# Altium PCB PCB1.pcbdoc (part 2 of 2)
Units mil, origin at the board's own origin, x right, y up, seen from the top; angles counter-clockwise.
Board outline 5331.95 x 5611.34 mil, 4 copper layers (Top Layer, GND, VCC, Bottom Layer); 134 components, 102 nets, 494 pads, 130 vias.
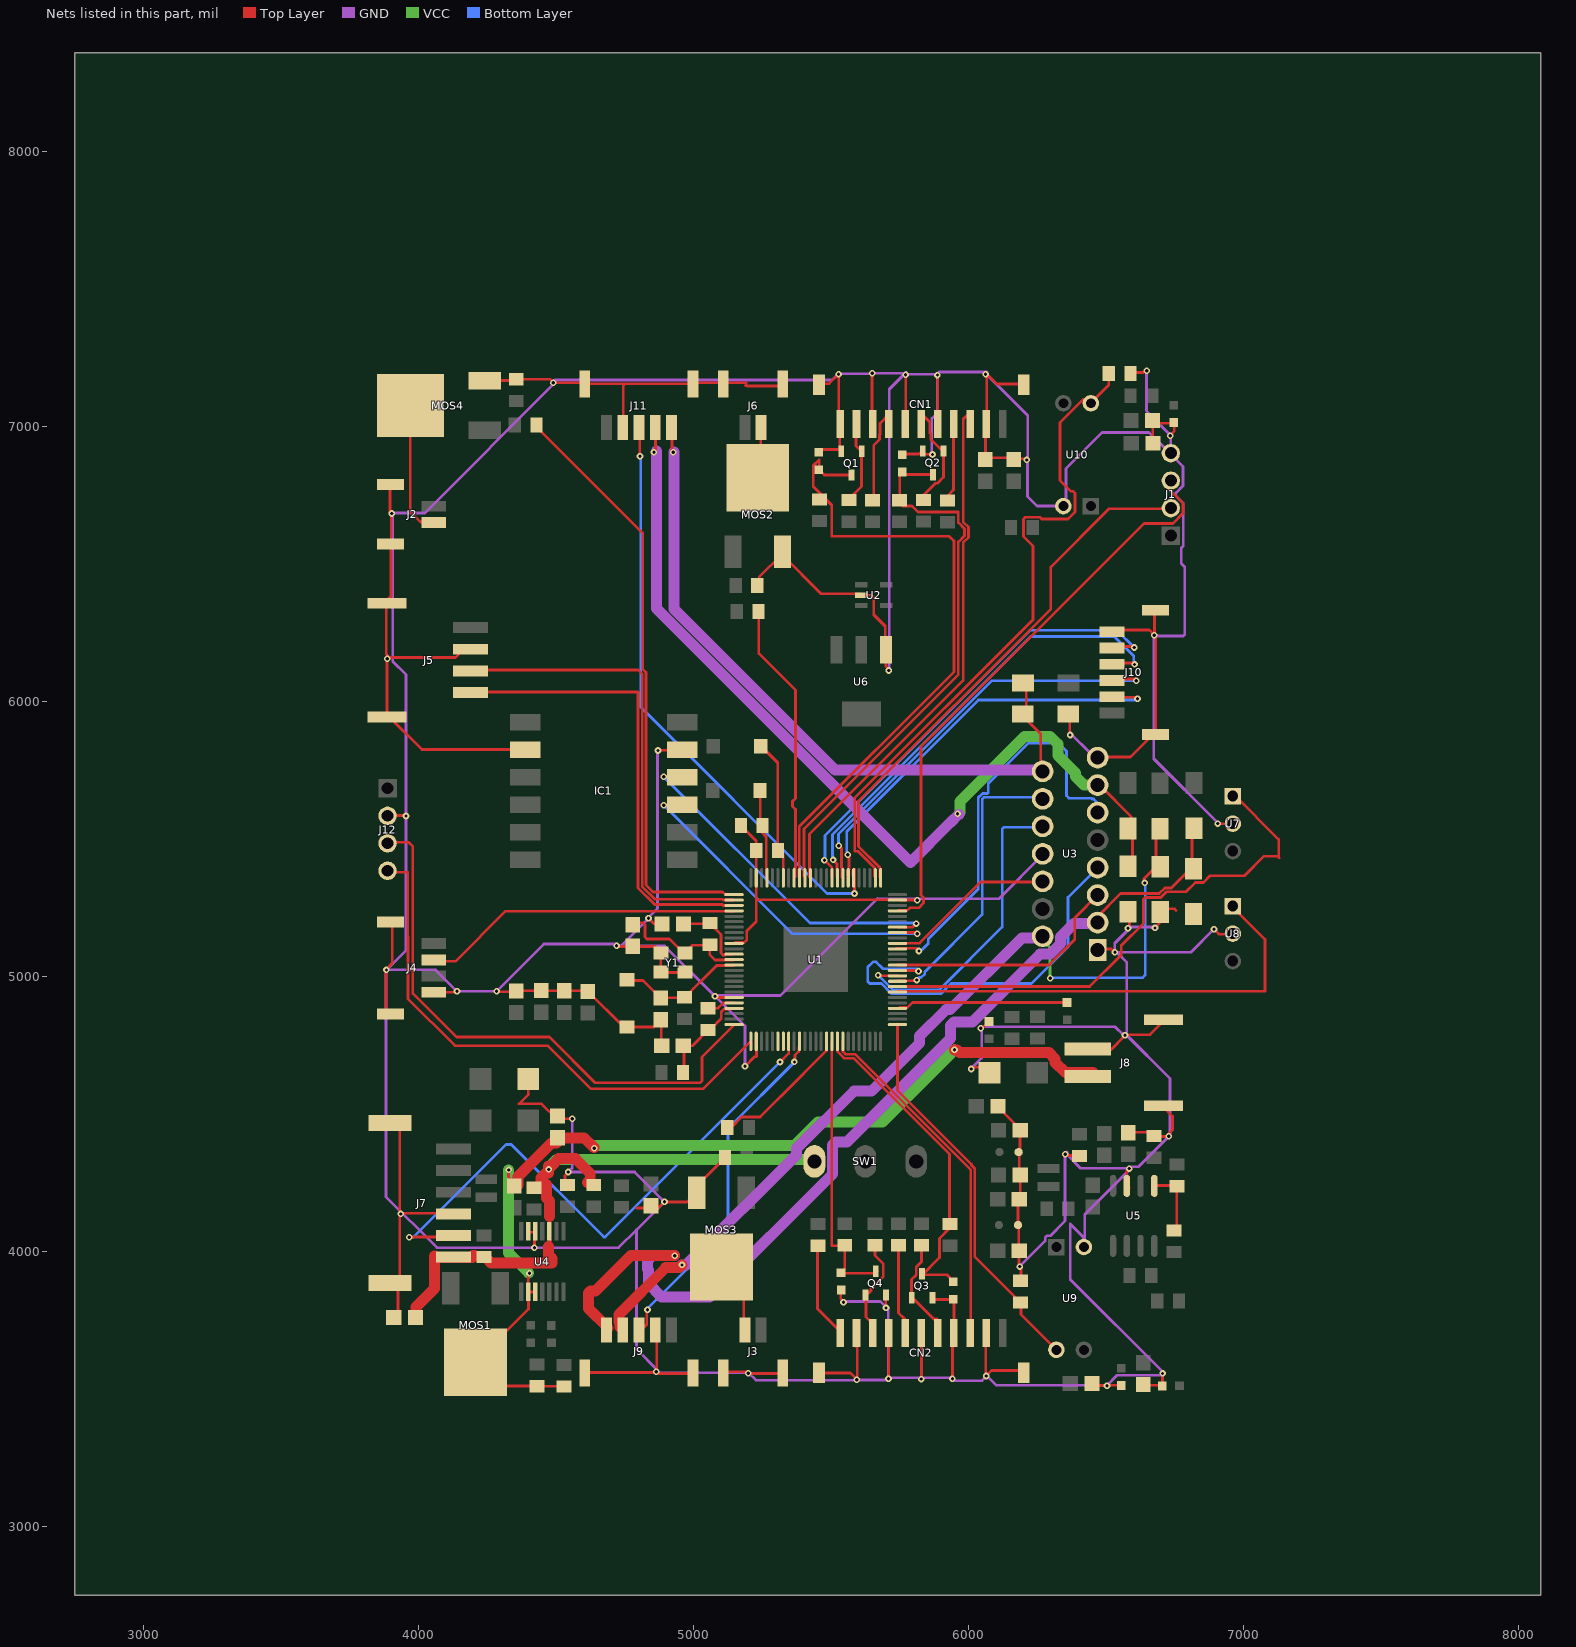
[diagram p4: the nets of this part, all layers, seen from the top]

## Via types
v1: diameter 24.02, hole 12.01, Top Layer to Bottom Layer, 130 vias

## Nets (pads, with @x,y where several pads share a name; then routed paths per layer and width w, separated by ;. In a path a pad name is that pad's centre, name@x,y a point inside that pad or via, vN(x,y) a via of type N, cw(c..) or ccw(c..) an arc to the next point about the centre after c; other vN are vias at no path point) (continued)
BAT0: J7.5 U1.33 | length 2084.2
  Top Layer w10: v1@3967.27,4053.06 4061.95,4053.06 J7.5@4066.07,4057.18 ; v1@5315.43,4689.12 5347.19,4720.88 U1.33@5347.19,4764.99
  Bottom Layer w10: v1@3966.79,4052.95 3982.35,4052.95 4319.1,4389.7 4338.14,4389.7 4674.89,4052.95 4678.68,4052.95 v1@5317.79,4692.07
  other v1: 3967.5,4052.88 5315.68,4689.91
BATTERY+: C12.1 J7.6 R14.1 R15.1 R16.1 SW1.1 U4.10 | length 2230.4
  Top Layer w10: 4204.74,3986.34 4214.22,3976.86 R16.1@4247.08,3976.86 ; 4449.08,4240.33 4462.17,4240.33 ; U4.10@4478.16,4046.06 4479.28,4044.95 4479.28,3984.03
  Top Layer w40: C12.1@3991.67,3760.1 3991.67,3798.69 4059.43,3866.45 4059.43,3984.11 ; J7.6@4078.26,3979.4 4197.79,3979.4 4204.74,3986.34 4199.09,3986.34 ; R16.1@4247.08,3976.86 4264.65,3959.29 4486.06,3959.29 4486.06,3976.01 4473.73,3988.33 4473.73,4019.01 ; R15.1@4446.57,4244.51 4446.57,4267.97 v1@4473.91,4295.34 ; 4466.31,4244.47 4466.31,4194.85 4477.28,4183.88 4477.28,4127.55 ; 4473.91,4286.39 v1@4473.91,4295.34 ; v1@4473.91,4311.21 v1@4473.91,4297.52 ; v1@4474.98,4298.58 v1@4473.91,4297.52 ; 4483.73,4311.21 4510.65,4338.13 4571.33,4338.13 4625.43,4284.02 4625.43,4261.49 R14.1@4615.97,4252.02 ; v1@4473.91,4295.34 v1@4473.91,4297.52
  VCC w40: v1(4474.29,4299.28) 4474.29,4306.18 4503.29,4335.18 5433.95,4335.18 SW1.1@5441.48,4327.65
BMQ-L1: J11.3 U1.81 | length 2175.6
  Top Layer w10: v1@4805.66,6894.2 J11.3@4805.66,6992.76 ; U1.81@5580.86,5367.84 5580.86,5385.26 5586.46,5390.86 5586.46,5303.15 v1(5586.56,5303.05)
  Bottom Layer w10: v1@4809.33,6886.4 4809.33,5980.35 5486.63,5303.05 v1(5586.56,5303.05)
  other v1: 4806.44,6893.22
BMQ-R1: J9.3 U1.35 | length 1241.1
  Top Layer w10: J9.3@4814.48,3719.83 4830.81,3736.16 v1@4830.81,3785.73 ; v1@5370.39,4694.8 5370.39,4715.34 5383.47,4728.42 5383.47,4742.61 U1.35@5386.46,4745.6
  Bottom Layer w10: v1@4836.19,3795.77 5126.85,4086.42 5126.85,4448.59 v1@5365.67,4687.41
  other v1: 4833.72,3788.84 5368.13,4690.28
BOOT0: KEY2.1 R7.1 U1.94 | length 517.9
  Top Layer w10: KEY2.1@5247.31,5838.57 5307.55,5778.34 R7.1@5307.55,5462.4 ; R7.1@5307.55,5454.56 R7.1@5307.55,5462.4 ; U1.94@5327.21,5361.59 5327.21,5442.74 R7.1@5307.55,5462.4
FAN_FB: J5.4 U1.3 | length 1709.6
  Top Layer w10: J5.4@4193.39,6035.97 4799.37,6035.97 4799.37,5323.14 4860.06,5262.45 5106.19,5262.45 5109.09,5259.56 5151.42,5259.56 5151.92,5259.06 U1.3@5163.63,5259.06
FAN_PWM: J5.3 U1.2 | length 1756
  Top Layer w10: J5.3@4193.17,6121.09 4198.81,6115.46 4800.24,6115.46 4814.21,6101.48 4814.21,5328.12 4860.2,5282.13 5105.7,5282.13 5108.7,5279.13 U1.2@5147.35,5279.13
FB: R41.1 R42.2 U5.5 | length 239.6
  Top Layer w10: U5.5@6675.98,4241.59 6677.03,4240.54 R42.2@6754.14,4240.54 ; R41.1@6747.02,4079.07 6759.15,4091.2 R42.2@6759.15,4235.1
FRONT1: J10.2 U1.82 | length 1497.1
  Top Layer w10: v1(5562,5443.4) 5567.02,5438.38 5567.02,5391.24 5562.85,5387.07 U1.82@5562.85,5366.12 ; J10.2@6537.01,6016.47 6612.53,6016.47 v1@6613.95,6017.89
  Bottom Layer w10: v1@5558.43,5442.77 5558.43,5528.53 6036.99,6007.09 v1@6612.96,6007.09
  other v1: 6615.95,6011.14
FRONT2: J10.3 U1.83 | length 1563.5
  Top Layer w10: v1(5529.54,5476.84) 5539.01,5467.38 5539.01,5398.35 5540.95,5396.4 5540.95,5362.29 U1.83@5546.22,5357.02 ; J10.3@6530.66,6082.82 6609,6082.82 v1@6611.83,6080
  Bottom Layer w10: v1@5528.79,5478.77 5528.79,5519 6086.75,6076.97 v1@6611.9,6076.97
  other v1: 6611,6076.31
FRONT3: J10.4 U1.84 | length 1687.3
  Top Layer w10: v1(5508.73,5424.97) 5523.01,5410.69 U1.84@5523.01,5362.67 ; J10.4@6529.95,6130.11 6541.24,6141.41 v1@6599.83,6141.41
  Bottom Layer w10: v1@5506.55,5424.77 5506.55,5516.88 6227.57,6237.9 6531.44,6237.9 6602.37,6166.96 v1@6602.37,6138.38
  other v1: 6605.36,6136.07
FRONT4: J10.5 U1.85 | length 1697.1
  Top Layer w10: v1(5477.19,5424) 5504.18,5397 U1.85@5504.18,5362.67 ; J10.5@6534.89,6201.4 6600.45,6201.4 v1(6604.16,6197.69)
  Bottom Layer w10: v1@5476.11,5421.51 5478.94,5424.33 5478.94,5513.97 6225.1,6260.14 6541.72,6260.14 v1(6604.16,6197.69)
GND: C1.2 C2.2 C3.2 C4.2 C5.1 C6.2 C7.1 C8.2 C9.1 C11.1 C12.2 C13.1 C14.1 C15.1 C17.2 C18.2 C19.2 C20.2 C21.2 C22.2 C24.2 C25.2 C26.2 C27.2 C28.2 CN1.2 CN1.5 CN1.7 CN1.9 CN1.11 CN1.12 CN1.13 CN2.2 CN2.4 CN2.6 CN2.8 CN2.10 CN2.12 CN2.13 D2.2 D3.2 D4.2 D5.2 D6.2 D7.2 IC1.5 IC1.8 J1.4 J2.3 J2.4 J3.3 J3.4 J4.4 J4.5 J4.6 J5.2 J5.5 J5.6 J6.3 J6.4 J7.4 J7.7 J7.8 J8.2 J8.3 J8.4 J9.4 J9.6 J9.7 J10.6 J10.7 J10.8 J11.4 J11.6 J11.7 J12.2 KEY1.2 LED1.1 LED4white.1 LED5white.1 LED-blue2.1 LED-blue3.1 LED-blue4.1 LED-blue.1 MOS2.3 MOS3.3 MOS4.3 Q1.2 Q2.2 Q3.2 Q4.2 R7.2 R8.2 R12.1 R19.2 R21.2 R23.2 R37.2 R39.2 R40.2 R43.1 U1.10 U1.20 U1.27 U1.74 U1.99 U2.2 U3.1 U3.8 U3.15 U4.12 U4.13 U5.7 U6.1 U7.2 U8.2 U9.2 U10.2 WHITE.1 Y1.1 Y1.2 Y1.4 | length 37316.1
  Top Layer w10: J5.5@3879.03,6362.11 3900.9,6383.99 J2.3@3900.9,6575.57 ; v1@3882.66,5027.65 3882.66,4876.11 J4.5@3897.72,4861.05 ; v1@3883.6,5027.65 3905.25,5049.3 J4.6@3905.25,5200.83 ; J5.5@3883.6,6355.69 3883.6,6173.1 v1@3890.19,6166.51 ; J5.6@3886.43,5949.09 v1@3886.43,6158.98 ; J12.2@3888.31,5586.73 3953.5,5586.73 v1(3955.44,5584.79) ; J5.6@3888.49,5951.08 4012.73,5826.85 IC1.8@4388.27,5826.85 ; v1@3889.9,6161.44 4135.56,6161.44 J5.2@4172.27,6198.15 ; J2.3@3896.78,6575.93 J2.3@3898.66,6577.81 ; v1@3896.78,6688.88 J2.4@3896.78,6785.82 ; J2.3@3901.49,6580.64 v1@3901.49,6685.11 ; C12.2@3902.43,3764.08 3926.43,3788.08 J7.7@3926.43,3862.9 ; J7.7@3932.08,3869.96 v1@3932.08,4138.21 ; v1@3932.08,4146.68 J7.8@3932.08,4492.57 ; v1@3937.72,4141.03 3939.13,4139.62 J7.4@4073.26,4139.62 ; J4.4@4059.61,4943.88 4137.61,4943.88 v1(4140.87,4947.14) ; MOS4.3@4244.56,7169.14 4352.48,7169.14 4356.87,7173.54 4478.6,7173.54 v1(4491.15,7161.01) J11.6@4598.45,7160.99 ; v1@4288.63,4945.67 4351.36,4945.67 C19.2@4357.58,4951.89 ; C19.2@4357.72,4948.7 C20.2@4439.71,4948.7 ; U4.13@4398.57,4074.31 4401.94,4070.94 U4.12@4422.44,4070.94 ; D2.2@4400.18,4620.95 4400.18,4572.27 ; 4400.85,4572.94 4400.18,4572.27 ; v1(4422.44,4014.63) U4.12@4422.44,4070.94 ; U4.12@4425.53,4070.94 U4.12@4422.44,4070.94 ; C20.2@4445.15,4948.7 C21.2@4525.89,4948.7 ; C9.1@4504.46,4482.51 4505.23,4483.28 v1(4559.98,4483.28) ; C9.1@4508.57,4480.27 4508.57,4480.04 4507.45,4478.92 4448.65,4537.72 4365.63,4537.72 4400.18,4572.27 ; C21.2@4531.74,4949.12 C22.2@4617.5,4949.12 ; R40.2@4533.49,4245.13 4533.49,4277.47 v1(4545.75,4289.73) ; J11.6@4600.33,7159.1 J11.6@4602.22,7157.22 ; J11.6@4601.59,7156.59 J11.7@5002.54,7156.59 ; J9.7@4603.63,3560.83 v1@4862.46,3560.83 ; C22.2@4615.82,4948.7 4747.17,4817.35 4857.61,4817.35 4883.96,4843.71 C4.2@4883.96,4744.99 ; v1@4720.98,5113.21 4724.11,5110.07 4862.79,5110.07 4883.49,5089.36 4882.24,5088.11 Y1.1@4882.24,5015.32 ; J11.4@4745.59,7000.35 4745.59,7150.95 4749.36,7154.71 ; 4793.27,4158.64 4872.85,4158.64 v1(4895.43,4181.22) 4977.61,4181.22 MOS3.3@5007.91,4211.52 ; v1@4837.2,5212.77 4857.28,5192.69 C1.2@4886.14,5192.69 ; J9.4@4858.69,3721.78 4867.17,3713.3 v1@4867.17,3571.18 ; v1@4864.34,3567.42 4874.69,3557.06 J9.6@4997.99,3557.06 ; v1@4875.03,5824.1 IC1.5@4947.82,5824.1 ; Y1.1@4884.12,5015.95 Y1.2@4970.08,5015.95 ; MOS3.3@5005.4,4211.52 5005.4,4230.97 R21.2@5114.58,4340.15 ; J11.7@5007.25,7160.36 5193.07,7160.36 5193.07,7150.95 ; v1(5079.26,4928.73) 5083.03,4924.97 U1.20@5147.03,4924.97 ; J3.4@5115.64,3563.65 v1@5193.76,3563.65 ; U1.10@5149.66,5122.12 5152.19,5124.65 5185.23,5124.65 5194.89,5134.32 5194.89,5167.35 5229.14,5201.6 U1.99@5229.14,5340.69 ; R8.2@5173.27,5550.14 5229.32,5494.09 5229.32,5457.7 U1.99@5229.32,5359.81 ; v1(5188.44,4674.03) 5223.49,4709.08 5228.28,4709.08 5229.97,4710.77 U1.27@5229.97,4763.69 ; 5189.84,7150.95 5193.07,7150.95 ; v1@5199.41,3562.71 5205.06,3557.06 J3.3@5325.53,3557.06 ; 5229.32,5281.94 5231.21,5280.06 U1.74@5743.85,5280.06 ; R19.2@5239.83,6420.59 5239.83,6453.85 MOS2.3@5322.34,6536.36 ; MOS2.3@5323.28,6537.3 MOS2.3@5322.34,6536.36 ; J6.4@5332.91,7150.95 5330.4,7148.44 5195.58,7148.44 5193.07,7150.95 ; CN2.13@5455.03,3558.83 5572.37,3558.83 v1@5596.21,3534.99 ; CN1.12@5456.91,7157.22 5494.56,7157.22 v1@5527.5,7190.17 ; LED-blue.1@5460.7,6908.14 5470.11,6917.55 Q1.2@5539.76,6917.55 ; CN1.11@5529.12,7058.25 v1@5529.12,7192.84 ; CN1.11@5533.17,7051.2 5533.17,6924.14 Q1.2@5539.76,6917.55 ; CN1.11@5534.67,7052.7 CN1.11@5534.77,7052.6 ; LED-blue4.1@5536.79,3859.14 5536.79,3829.02 v1@5542.65,3823.16 ; Q1.2@5540.7,6917.55 Q1.2@5539.76,6917.55 ; CN2.2@5590.95,3657.77 5596.6,3652.13 v1@5596.6,3538.24 ; U2.2@5607.53,6392.98 5465.72,6392.98 MOS2.3@5322.34,6536.36 ; U2.2@5614.22,6390.05 5616.77,6387.5 5649.4,6387.5 5656.47,6380.43 5656.47,6316.85 5698.3,6275.02 U6.1@5698.3,6206.83 ; CN1.9@5650.54,7051.66 5650.54,7194.69 v1(5651.03,7195.18) ; v1@5700.35,3794.72 Q4.2@5700.35,3844.08 ; U6.1@5701.33,6184.75 5701.33,6128.28 v1@5707.6,6122.01 ; v1@5710.49,3538.24 5711.43,3539.18 CN2.4@5711.43,3657.77 ; U1.74@5749.22,5279.08 5812.8,5279.08 v1@5815.03,5276.85 ; LED-blue2.1@5764.91,6901.04 5821.38,6901.04 Q2.2@5837.07,6916.73 ; CN1.7@5768.69,7053.06 5773.39,7057.77 v1@5773.39,7193.3 ; CN2.6@5824.37,3666.24 5830.02,3660.6 v1@5830.02,3542 ; Q2.2@5835.18,6909.83 5844.59,6900.41 v1@5867.18,6900.41 ; Q3.2@5871.86,3830.48 5876.47,3825.88 LED-blue3.1@5945.07,3825.88 ; CN1.5@5888.22,7056.83 5889.16,7057.77 v1@5889.16,7190.48 ; v1(5942.82,3537.95) 5942.82,3659.84 CN2.8@5945.65,3662.66 ; CN2.8@5948.42,3657.3 LED-blue3.1@5948.42,3829.23 ; v1@6006.65,4670.8 6060.3,4670.8 D3.2@6082.88,4648.22 ; v1@6048.06,4817.63 6056.53,4817.63 LED1.1@6077.24,4838.34 ; C25.2@6060.46,6887.41 C25.2@6061.4,6888.35 ; CN2.10@6060.48,3672.07 6064.24,3668.31 v1@6064.24,3548.77 ; v1@6061.4,7192.36 v1@6066.15,7187.61 ; C25.2@6062.34,6887.41 6163.99,6887.41 C26.2@6164.93,6888.35 ; C25.2@6063.28,6890.23 CN1.2@6063.28,7046.47 ; v1@6065.56,3548.16 6085.64,3568.24 CN2.12@6206.11,3568.24 ; CN1.2@6067.99,7052.12 v1@6067.99,7185.77 ; v1@6069.64,7191.11 6104.46,7156.28 CN1.13@6199.52,7156.28 ; C17.2@6104.53,4530.56 C18.2@6187.36,4447.74 ; C26.2@6164.93,6884.59 6205.41,6884.59 v1@6210.11,6879.88 ; C8.2@6177.95,4093.84 6183.59,4088.2 C14.1@6183.59,4002.55 ; C8.2@6181.71,4093.84 6181.71,4178.55 C7.1@6185.48,4182.32 ; C6.2@6183.59,4359.27 C6.2@6184.53,4360.21 ; C14.1@6184.53,3996.9 6184.53,3953.6 v1@6187.36,3950.78 ; C5.1@6185.48,4286.79 C6.2@6185.48,4359.27 ; C7.1@6186.42,4193.61 6189.24,4196.44 C5.1@6189.24,4280.2 ; C6.2@6188.3,4363.97 C18.2@6188.3,4438.33 ; R37.2@6192.06,3885.84 v1@6192.06,3942.31 ; v1@6351.62,4356.96 6358.52,4350.05 R12.1@6403.7,4350.05 ; D5.2@6369.91,5953.68 6369.91,5883.1 v1@6372.03,5880.98 ; J8.2@6434.45,4734.69 6519.16,4734.69 v1@6572.49,4788.03 ; C13.1@6457.29,3520.67 6464.82,3513.14 v1@6501.64,3513.14 ; U3.1@6468.93,5101.38 6521.63,5101.38 v1@6531.99,5091.03 ; U3.15@6478.78,5798.92 6589.84,5798.92 J10.8@6668.9,5877.99 ; v1@6504.73,3513.95 6551.79,3513.95 WHITE.1@6555.55,3517.71 ; J10.6@6525.4,6260.95 6659.05,6260.95 v1@6674.58,6245.42 ; v1@6574.42,4789.42 6661.01,4789.42 J8.3@6717.49,4845.89 ; v1(6581.31,5176.23) 6586.96,5181.89 D4.2@6586.96,5218.59 ; v1@6585.67,4302.99 6576.79,4294.12 6576.79,4242.22 U5.7@6586.3,4232.72 ; C24.2@6586.3,4434.45 6660.34,4434.45 R43.1@6676.65,4418.13 ; R39.2@6598.34,7197.92 6637.87,7197.92 v1@6650.11,7210.15 ; C15.1@6637.44,3523.36 6646.85,3513.95 LED5white.1@6708.97,3513.95 ; C28.2@6670.82,7022.85 C28.2@6671.76,7021.91 ; C27.2@6671.76,6943.79 C28.2@6671.76,7021.91 ; R43.1@6676.65,4419.39 6727.48,4419.39 v1@6728.73,4420.64 ; v1@6677.88,6240.24 v1@6677.88,6242.12 ; v1@6677.88,6247.77 6677.88,6326.83 J10.7@6681.64,6330.6 ; J10.8@6682.58,5881.64 v1@6682.58,6242.12 ; v1@6684.37,5183.29 6696.37,5195.29 D7.2@6696.37,5222.12 ; D7.2@6687.9,5247.53 6750.01,5247.53 6756.36,5241.17 ; LED5white.1@6707.09,3518.65 6707.09,3556.3 v1@6708.97,3558.18 ; J8.4@6708.03,4527.63 6743.16,4492.49 6743.16,4442.29 v1@6726.85,4425.98 ; v1@6735.76,6971.09 6749.88,6985.21 LED4white.1@6749.88,7013.44 ; LED4white.1@6748.94,7013.44 6680.23,7013.44 C28.2@6671.76,7021.91 ; v1(6894.16,5173.21) 6912.34,5155.03 U8.2@6963.06,5155.03 ; v1@6906.59,5558.81 6908.47,5556.92 U7.2@6962.12,5556.92
  GND w10: 3881.25,4200.73 4067.36,4014.63 v1(4422.44,4014.63) 4728.84,4014.63 4793.78,4079.57 ; 3882.66,4202.14 v1@3882.66,5023.82 ; v1@3885.49,5025.23 4062.78,5025.23 v1(4140.87,4947.14) v1(4284.65,4947.14) 4456.68,5119.17 v1@4718.71,5119.17 ; v1@3888.31,5028.05 3955.44,5095.18 v1(3955.44,5584.79) 3955.44,6098.85 3906.66,6147.62 v1@3906.66,6684.11 ; v1@3908.07,6686.93 4023.84,6686.93 v1@4499.62,7162.71 ; v1@4496.74,7170.62 5504.78,7170.62 v1@5530.19,7196.03 ; v1(4559.98,4483.28) 4559.98,4303.95 v1(4545.75,4289.73) 4786.92,4289.73 v1(4895.43,4181.22) 4793.78,4079.57 ; v1@4716.83,5109.76 v1@4725.3,5109.76 ; v1@4725.3,5112.58 4737.54,5112.58 ; v1@4836.25,5214.35 4849.67,5228.41 4869.67,5248.41 v1@4869.67,5824.43 ; v1@4837.26,5212.3 4737.54,5112.58 ; v1@4870.46,3559.77 v1@5192.35,3559.77 ; v1@4870.93,3568.24 4793.78,3645.4 4793.78,4079.57 ; v1@5074.49,4933.75 4895.66,5112.58 4737.54,5112.58 ; v1@5079.8,4930.28 5188.44,4821.65 v1(5188.44,4674.03) ; v1@5080.05,4931.48 5317.17,4931.48 5670.12,5284.43 v1@5821.25,5283.44 ; v1@5201.29,3558.95 5227.65,3532.59 v1@5590.01,3532.59 ; v1@5530.27,7193.02 5640.39,7193.02 v1@5641.33,7193.96 ; v1@5547.25,3818.56 5681.53,3818.56 5699.52,3800.57 5709.66,3793.78 v1@5709.66,3545.82 ; v1@5598.48,3533.53 5703.9,3533.53 5711.43,3541.06 v1@5827.2,3541.06 ; v1(5651.03,7195.18) v1@5771.04,7195.18 ; v1@5712.94,6115.64 5712.94,7137.08 v1@5771.04,7195.18 ; v1@5771.45,7193.25 5773.57,7191.13 5885.1,7191.13 5893.57,7199.6 v1@6068.64,7199.6 ; v1@5775.06,7199.2 v1@5771.04,7195.18 ; v1@5820.3,5283.44 v1@5821.25,5283.44 ; v1@5831.9,3541.06 5939.2,3541.06 v1@5940.14,3540.12 ; v1@5867.81,6902.3 5867.81,7030.93 5888.52,7051.64 v1@5888.52,7180.89 ; v1@5946.12,3530.89 6050.59,3530.89 v1@6067.53,3547.83 ; v1@6017,4672.69 6049,4704.69 v1@6049,4820.46 ; v1@6050.88,4818.1 6534.66,4818.1 v1@6564.78,4787.98 ; v1@6065.81,7193.02 6216.41,7042.42 v1@6216.41,6881.48 ; v1@6068.95,3547.83 6102.83,3513.95 6505.2,3513.95 6541.9,3550.66 v1@6708.5,3550.66 ; v1@6190.18,3949.37 6280.03,4039.22 6280.03,4051.62 6286.46,4058.05 6298.87,4058.05 6352.07,4111.26 v1@6352.07,4356.91 ; v1@6215.47,6879.59 6215.47,6747.46 6250.34,6712.58 U10.2@6350.9,6712.58 ; U3.8@6272.08,5444.39 6111.13,5283.44 v1@5821.25,5283.44 ; U10.2@6349.02,6710.46 U10.2@6350.9,6712.34 ; U10.2@6355.71,6717.23 6355.71,6848.06 6487.48,6979.83 6658.07,6979.83 J1.4@6737.01,6900.89 ; v1@6359.24,4362.44 6359.24,4353.58 6409.19,4303.62 6584.25,4304.56 v1@6583.32,4304.56 ; v1@6372.74,5884.51 6446.15,5811.1 U3.15@6468.03,5811.1 ; U9.2@6419.88,4020.44 6419.88,4052.44 6371.47,4100.84 6371.47,3899.13 v1@6708.66,3561.94 ; U9.2@6423.64,4022.32 6423.64,4134.33 v1@6587.41,4298.1 ; v1@6533.33,5094.11 6533.33,5121.98 v1@6580.58,5169.24 ; v1@6571.41,4792.7 6733.77,4630.34 v1@6733.77,4429.87 ; v1@6577.06,4791.29 6577.06,5052.47 6540.35,5089.18 6810.13,5089.18 v1(6894.16,5173.21) ; v1@6585.3,5180.58 v1@6685.01,5180.58 ; v1@6590.23,4309.39 6620.35,4309.39 v1@6735.18,4424.22 ; v1@6648.54,7203.1 6648.54,7057.68 v1@6733.25,6972.97 ; v1@6674.89,6244.01 6674.89,5792.93 v1@6903.61,5564.22 ; v1@6680.54,6239.77 6782.19,6239.77 6787.97,6245.55 6787.97,6490.61 6775.1,6503.48 6775.1,6560 6782.79,6567.69 6782.79,6721.61 6755.49,6748.9 6755.49,6760 6781.53,6786.04 6781.53,6856.37 J1.4@6737.01,6900.89 ; J1.4@6737.01,6904.45 v1@6737.01,6966.85 ; J1.4@6739.72,6903.59 J1.4@6737.01,6900.89
  other v1: 6504.83,3512.95 5594.72,3534.23 5710.17,3537.36 5829.39,3536.74 6066.23,3547.78 6707.19,3557.19 5199.9,3558.34 4865.91,3563.72 5701.19,3795.55 5546.41,3816.47 6187.64,3945.91 3936.47,4137.38 6586.09,4302.31 6353.61,4354.08 6729.78,4420.28 6011.32,4664.68 6570.58,4787.02 6046.04,4812.97 3884.07,5024.94 6533.87,5089.14 4721.19,5112.37 6679.43,5177.65 4837.2,5213.18 5814.75,5278.18 6907.88,5557.28 4871.9,5822.85 6370.62,5879.57 5710.85,6113.85 3886.9,6157.21 6676.35,6242.01 3903.84,6685.23 6212.94,6879.88 5870.32,6899.79 6734.7,6967.36 5888.22,7188.6 5772.45,7189.54 5528.68,7191.42 6063.28,7191.42 6649.05,7203.92
IR_BT_F: LED-blue2.2 Q2.3 R29.1 U1.90 | length 2041.3
  Top Layer w10: U1.90@5406.24,5361.24 5403.15,5364.33 5403.15,5538.02 5964.28,6099.16 5964.28,6581.41 5986.98,6604.1 5986.98,6629.65 5964.28,6652.35 5964.28,6690.43 5817.27,6690.43 5795.17,6712.53 5762.5,6712.53 5750.85,6724.18 5750.85,6828.69 LED-blue2.2@5759.32,6837.16 ; LED-blue2.2@5760.97,6837.58 5772,6826.54 Q2.3@5872.12,6826.54
IR_BT_FI-: CN1.6 Q2.1 R28.2 | length 395.2
  Top Layer w10: CN1.6@5827.98,7049.65 5860.45,7017.18 5860.45,6977.69 5864.34,6973.79 5864.34,6954.48 5903.19,6915.63 Q2.1@5906.02,6915.63 ; R28.2@5839.89,6745.34 5839.89,6731.68 5840.94,6755.15 5880.43,6794.65 5887.49,6794.65 5909.96,6817.12 Q2.1@5909.96,6912.47
IR_BT_FO+: CN1.4 R27.2 | length 326.5
  Top Layer w10: R27.2@5925.03,6732.73 5926.08,6733.78 5926.08,6751.21 5946.23,6771.36 CN1.4@5946.23,7050.43
IR_BT_L: LED-blue.2 Q1.3 R26.1 U1.91 | length 2388.5
  Top Layer w10: U1.91@5385.51,5362.6 5384.17,5363.93 5384.17,5391 5385.73,5392.56 5385.73,5545.95 5948.29,6108.51 5948.29,6585.71 5946.88,6587.11 5945.94,6587.11 5930.89,6602.16 5503.73,6602.16 5503.73,6714.98 5436.62,6783.15 5436.62,6858.73 5458.1,6880.2 5458.1,6844.06 5476.92,6825.24 Q1.3@5579.51,6825.24
IR_BT_LI-: CN1.10 Q1.1 R25.2 | length 345.5
  Top Layer w10: R25.2@5563.88,6735.88 5611.97,6783.97 Q1.1@5611.97,6912.47 ; CN1.10@5592.26,7052.8 5592.26,6930.61 Q1.1@5611.18,6911.69
IR_BT_LO+: CN1.8 R24.2 | length 341.5
  Top Layer w10: R24.2@5652.96,6733.52 5656.87,6737.42 5656.87,6933.7 5677.65,6954.48 5677.65,6972.1 5679.05,6973.5 5679.05,7013.07 5710.51,7044.53 CN1.8@5710.51,7051.22
IR_BT_R: LED-blue3.2 Q3.3 R32.1 U1.42 | length 1209.1
  Top Layer w10: U1.42@5524.42,4765.71 5524.42,4727.98 5548.43,4703.97 5583.53,4703.97 5932.19,4355.31 5932.19,4099.83 R32.1@5931.25,4098.88 ; Q3.3@5829.51,3912.22 5895.62,3978.32 5895.62,4048.43 5933.05,4085.86 R32.1@5933.05,4098.27 ; Q3.3@5834.24,3916.42 5922.01,3916.42 LED-blue3.2@5947.24,3891.19
IR_BT_RI-: CN2.7 Q3.1 R31.2 | length 428.2
  Top Layer w10: Q3.1@5794.3,3830.23 Q3.1@5795.35,3829.18 ; Q3.1@5794.3,3834.96 5794.3,3898.55 5811.03,3915.28 5811.03,3944.36 5830.04,3963.37 R31.2@5830.04,4019.43 ; Q3.1@5794.83,3834.96 5874.71,3755.07 5886.27,3755.07 5893.34,3748 5893.34,3738 5886.8,3731.46 CN2.7@5886.8,3657.84
IR_BT_RO+: CN2.5 R30.2 | length 340.1
  Top Layer w10: R30.2@5746.47,4018.38 5746.47,3777.67 5768.02,3756.12 5768.02,3690.95 CN2.5@5765.39,3688.33
IR_CC_L1: CN1.3 U1.89 | length 1949.1
  Top Layer w10: U1.89@5425.92,5359.43 5422.84,5362.51 5422.84,5518.57 5981.87,6077.6 5981.87,6579.18 6000.99,6598.3 6000.99,6635.46 5981.87,6654.58 5981.87,7027.74 CN1.3@6004.57,7050.43
IR_CC_L2: U1.58 U7.1 | length 1951.1
  Top Layer w10: U1.58@5743.68,4964.59 6441.84,4964.59 6556.86,5079.62 6556.86,5113.7 6637.48,5194.32 6637.48,5282.16 6643.91,5288.59 6700.62,5288.59 6721.14,5309.11 6792.37,5309.11 6826.4,5343.15 6855.87,5343.15 6880.23,5367.51 7005.38,5367.51 7076.65,5438.77 7124.56,5438.77 7130.86,5432.47 ; U7.1@6968.5,5660.71 7129.45,5499.77 7129.45,5433.88
IR_CC_R1: CN2.9 U1.43 | length 1322.5
  Top Layer w10: U1.43@5544.28,4766.56 5544.16,4766.44 5544.16,4728.06 5553.82,4718.4 5588.92,4718.4 6009.71,4297.61 6009.71,3663.44 CN2.9@6005.52,3659.24
IR_CC_R2: U1.57 U8.1 | length 1691.8
  Top Layer w10: U1.57@5742.48,4946.92 7079.32,4946.92 ; U8.1@6960.1,5255.47 7079.32,5136.25 7079.32,4949.89
IR_SD: LED-blue4.2 Q4.3 R35.1 U1.41 | length 1019.1
  Top Layer w10: U1.41@5504.08,4762.78 5504.08,4021.21 R35.1@5548.23,4021.21 ; LED-blue4.2@5536.6,3924.3 5551.58,3939.28 R35.1@5551.58,4019.69 ; LED-blue4.2@5542.12,3921.94 5660.37,3921.94 5668.25,3929.82 Q4.3@5670.62,3929.82
IR_SD_I-: CN2.3 Q4.1 R34.2 | length 403
  Top Layer w10: Q4.1@5626.03,3837.5 Q4.1@5628.22,3839.69 ; Q4.1@5628.22,3841.27 Q4.1@5628.22,3839.69 ; Q4.1@5629.01,3840.48 5646.35,3857.82 5646.35,3865.27 5691.33,3910.24 5691.33,3955.75 5661.16,3985.92 R34.2@5661.16,4022.06 ; CN2.3@5647.67,3671.51 5650.29,3674.14 5650.29,3740.36 5628.22,3762.43 Q4.1@5628.22,3839.69
IR_SD_O+: CN2.1 R33.2 | length 390.8
  Top Layer w10: R33.2@5454.18,4024.03 5452.3,4022.15 5452.3,3792.49 5530.42,3714.37 CN2.1@5530.42,3666.37
IRHIT_L: R37.1 U1.51 U9.3 | length 1424.8
  Top Layer w10: U1.51@5743.36,4827.82 5743.36,4586.87 6012.55,4317.69 6012.55,4314.59 6023.73,4303.41 6023.73,3982.73 R37.1@6192.32,3814.14 ; R37.1@6191.89,3814.14 6191.89,3771.35 U9.3@6320.84,3642.4
IRHIT_R: R39.1 U1.77 U10.3 | length 2458.8
  Top Layer w10: U1.77@5663.33,5360.34 5659.06,5364.61 5659.06,5396.4 5598.92,5456.54 5588.41,5456.54 5587.19,5457.77 5587.19,5649.74 6236.05,6298.59 6236.05,6566.99 6201.24,6601.8 6201.24,6665.11 6207.67,6671.54 6261.36,6671.54 6267.79,6665.11 6363.1,6665.11 6388.18,6690.19 6388.18,6759.29 6381.74,6765.72 6373.34,6765.72 6334.42,6804.64 6334.42,7016.15 6417.97,7099.69 U10.3@6456.3,7099.69 ; U10.3@6457.16,7098.83 6511.59,7153.26 R39.1@6511.59,7197.19
LB_I: R18.2 U1.92 | length 1034.8
  Top Layer w10: R18.2@5238.54,6329.32 5238.54,6176.14 5371.72,6042.96 5371.72,5648.64 5361.49,5638.42 5361.49,5619.37 5371.72,5609.15 5371.72,5398.37 5370.16,5396.81 5370.16,5363.05 U1.92@5367.15,5360.04
LB_O: J6.1 MOS2.2 | length 184.3
  Top Layer w10: MOS2.2@5230.29,6819.59 5245.82,6835.12 J6.1@5245.82,6997.48
LW_O1: D4.1 D12.2 J11.2 U3.13 | length 3286.2
  Top Layer w10: v1@4854.68,6909.66 4863.04,6918.03 J11.2@4863.04,6989.14 ; U3.13@6480.38,5695.03 6592.61,5582.8 D12.2@6592.61,5533.39 ; D4.1@6584.84,5401.4 6597.55,5414.11 D12.2@6597.55,5524.22
  GND w40: v1@4866.3,6911.92 4866.3,6338.99 5789.54,5415.74 5934.98,5561.18 5935.95,5561.18 v1@5965.79,5591.01
  VCC w40: v1@5969.9,5596.66 5969.9,5638.24 6205.67,5874 6298.07,5874 6326.26,5845.81 6326.26,5805.03 6390.31,5740.98 6390.31,5728.43 6421.37,5697.37 U3.13@6465.92,5697.37
  other v1: 5961.43,5592.9 4856.96,6907.73
LW_O2: D5.1 D13.2 J11.1 U3.14 | length 2582.7
  Top Layer w10: J11.1@4922.44,6983.7 4922.44,6913.01 v1@4925.37,6910.08 ; D5.1@6190.63,5955.8 6264.04,5882.39 U3.14@6264.04,5739.11 ; D13.2@6216.98,6051.56 6211.66,6046.23 6211.66,5967.95 D5.1@6223.33,5956.27
  GND w40: v1@4929.83,6908.74 4929.83,6337.7 5516.12,5751.41 6271.4,5751.41 U3.14@6273.52,5749.29
  other v1: 4927.65,6907.94
LWI1: U1.60 U3.10 | length 1142.6
  Top Layer w10: v1@5673.19,5005.58 5674.86,5003.9 U1.60@5745.56,5003.9
  Bottom Layer w10: v1@5674.37,5005.3 5727.31,4952.36 5894.93,4952.36 6123.64,5181.07 6123.64,5536.85 6130.71,5543.92 6260.6,5543.92 U3.10@6266.23,5549.55
  other v1: 5672.35,5005.58
LWI2: U1.59 U3.12 | length 1051.8
  Top Layer w10: U1.59@5744.3,4985.5 5810.39,4985.5 v1@5813.74,4988.84
  Bottom Layer w10: v1@5810.19,4986.02 5821.1,4996.94 5828.88,4996.94 5842.34,5010.41 5842.34,5018.18 6050.82,5226.66 6050.82,5645.7 6057.89,5652.77 6256.96,5652.77 U3.12@6262.59,5658.41
  other v1: 5812.49,4988.01
MAGNET: J4.2 U1.4 | length 1167.5
  Top Layer w10: J4.2@4056.92,5058.09 4058.8,5056.2 4135.04,5056.2 4317.43,5238.59 U1.4@5148.1,5238.59
NRST: C3.1 KEY1.1 R3.1 U1.14 | length 462.1
  Top Layer w10: KEY1.1@4760.92,4986.66 4817.39,4986.66 4881.39,4922.66 4882.34,4923.6 R3.1@4968.93,4923.6 ; R3.1@4968.93,4924.54 5085.64,5041.25 U1.14@5147.76,5041.25
PA6PWM: U1.31
PA7PWM: U1.32
PA9(U1TX): IC1.3 U1.68 | length 1257.4
  Top Layer w10: v1(4892.67,5624.28) 4893.92,5625.53 IC1.3@4960.25,5625.53 ; U1.68@5743.14,5161.22 5809.6,5161.22 v1(5814.59,5156.23)
  Bottom Layer w10: v1(4892.67,5624.28) 5360.71,5156.23 v1(5814.59,5156.23)
PA10(U1RX): IC1.4 U1.69 | length 1282.2
  Top Layer w10: v1(4892.67,5727.18) IC1.4@4960.25,5727.18 ; U1.69@5741.89,5180.46 5798.62,5180.46 v1(5811.64,5193.49)
  Bottom Layer w10: v1(4892.67,5727.18) 5424.68,5195.17 v1@5811.81,5195.17
PA13(SWDIO): J1.3 U1.72 | length 2130.2
  Top Layer w10: U1.72@5744.4,5240.91 5777.86,5240.91 5787.82,5250.87 5811.27,5250.87 5811.5,5250.64 5821.5,5250.64 5828.57,5257.71 5828.57,5259.48 5837.75,5268.65 5837.75,5287.7 5828.57,5296.88 5828.57,5837.15 6640.32,6648.9 6744.39,6648.9 6781.53,6686.04 6781.53,6722.86 6724.24,6780.16 6724.24,6791.51 J1.3@6736.98,6804.26
PA14(SWCLK): J1.2 U1.76 | length 1972.4
  Top Layer w10: U1.76@5681.05,5359.74 5678.75,5362.05 5678.75,5396.4 5673.08,5402.08 5673.08,5402.21 5601.2,5474.08 5601.2,5638.8 6300.77,6338.37 6300.77,6490.91 6512.24,6702.37 J1.2@6731.57,6702.37
PB15: LED2.1 U1.54 | length 618.5
  Top Layer w10: U1.54@5748.17,4885.44 5751.17,4888.43 5779.71,4888.43 5797.42,4906.15 LED2.1@6358.08,4906.15
PE0: KEY3.1 R8.1 U1.97 | length 327.1
  Top Layer w10: KEY3.1@5244.17,5676.06 5244.17,5556.21 R8.1@5251.39,5548.99 ; R8.1@5251.7,5549.31 R8.1@5251.7,5548.68 ; R8.1@5252.33,5548.05 R8.1@5251.7,5548.68 ; U1.97@5269.27,5360.44 5265.51,5364.2 5265.51,5509.15 5251.7,5522.95 R8.1@5251.7,5548.68
PH0(OSCIN): C1.1 R1.2 U1.12 | length 271.2
  Top Layer w10: C1.1@4965.16,5193.1 5058.65,5193.1 5059.91,5194.35 5100.7,5153.57 5100.7,5086.43 5107.77,5079.35 5117.77,5079.35 5120.45,5082.03 U1.12@5147.76,5082.03
PH1(OSCOUT): C2.1 R1.1 U1.13 Y1.3 | length 496.9
  Top Layer w10: C2.1@4782.57,5188.08 4783.5,5187.14 4797.64,5187.14 4807.22,5196.73 4817.22,5196.73 4824.29,5189.65 4824.29,5144.65 4831.36,5137.57 4913.56,5137.57 4966.9,5084.24 4997.64,5114.98 5059.91,5114.98 5059.91,5080.78 5079.36,5061.33 U1.13@5147.13,5061.33
PUMP_I: R22.2 U1.1 | length 2192.9
  Top Layer w10: R22.2@4430.17,7008.96 4430.17,7000.23 4815.99,6614.41 4815.99,6119.53 4828.23,6107.29 4828.23,5333.93 4853.42,5308.73 5106.76,5308.73 5116.76,5298.73 5146.14,5298.73 5146.55,5298.32 5165.43,5298.32 U1.1@5166.17,5297.58
PUMP_O: J2.2 MOS4.2 | length 488.2
  Top Layer w10: MOS4.2@3970.99,7080.87 3970.99,6691.21 4007.7,6654.5 J2.2@4054.28,6654.5
RB_I: R20.2 U1.40 | length 515.3
  Top Layer w10: R20.2@5120.7,4452.7 5138.39,4452.7 5175.65,4489.95 5243.44,4489.95 5308.15,4554.67 5308.52,4554.67 5321.98,4568.14 5321.98,4568.5 5485.25,4731.76 5485.25,4765.82 U1.40@5484.64,4766.43
RB_O: J3.1 MOS3.2 | length 266
  Top Layer w10: MOS3.2@5103.05,3946.52 5183.99,3865.58 J3.1@5183.99,3714.04
RW_O1: D7.1 D11.2 J9.2 U3.2 | length 3252.4
  Top Layer w10: v1@6639.9,5345.64 6638.9,5346.64 6638.9,5356.64 D7.1@6685.78,5403.52 ; D7.1@6683.66,5403.52 D11.2@6683.66,5544.69
  Top Layer w40: J9.2@4742.1,3717.62 4733.41,3726.31 4733.41,3741.5 4730.11,3744.8 4730.11,3771.84 4900.02,3941.75 4950.62,3941.75 v1@4959.85,3950.99
  GND w40: v1@4959.85,3950.99 4974.36,3950.99 5375.65,4352.28 5375.65,4375.27 5584.06,4583.69 5648.96,4583.69 5823.6,4758.33 5823.6,4784.01 5919.67,4880.08 5934.38,4880.08 6195.35,5141.05 6266,5141.05 U3.2@6272.97,5148.02
  VCC w10: U3.2@6269.74,5135.14 6298.09,5106.78 v1@6298.09,4994.8
  Bottom Layer w10: v1@6300.27,4996.06 6633.97,4996.06 6643.9,5005.98 v1@6643.9,5339.11
  other v1: 4959.02,3951.82 6298.77,4994.56 6642.72,5341.4
RW_O2: D6.1 D10.2 J9.1 U3.3 | length 3613.3
  Top Layer w10: U3.3@6471.2,5196 6471.2,5219.69 6554.12,5302.61 6694.81,5302.61 6715.33,5323.13 6738.56,5323.13 D6.1@6813.3,5397.87 ; D6.1@6807.4,5400.69 6814.46,5407.75 D10.2@6814.46,5531.04
  Top Layer w40: J9.1@4689.39,3723.27 4619.27,3793.39 4619.27,3849.96 4625.7,3856.39 4644.63,3856.39 4774.01,3985.77 v1(4932.39,3985.77)
  GND w40: v1(4932.39,3985.77) 4851.29,3985.77 4833.18,3967.66 4833.18,3936.18 4836.6,3932.76 4836.6,3883.73 4885.05,3835.28 5059.87,3835.28 5506.35,4281.76 5506.35,4387.67 5517.34,4398.65 5559.05,4398.65 5935.21,4774.81 5935.21,4822.59 5948.67,4836.06 6015.4,4836.06 6261.27,5081.92 6298.06,5081.92 6336.35,5120.21 6336.35,5145.37 6384.49,5193.51 U3.3@6472.43,5193.51
RWI1: U1.62 U3.5 | length 881.2
  Top Layer w10: U1.62@5742.95,5042.92 6294.5,5042.92 6387.68,5136.1 6387.68,5214.22 U3.5@6472.39,5298.93
RWI2: U1.61 U3.7 | length 1492.4
  Top Layer w10: U1.61@5741.79,5023.15 5816.14,5023.15 v1(5819.35,5019.93)
  Bottom Layer w10: v1@5819.88,5029.03 5690,5029.03 5664.59,5054.44 5654.59,5054.44 5634.94,5034.79 5634.94,4982.44 5642.01,4975.37 5684.48,4975.37 5721.51,4938.34 5900.73,4938.34 5937.76,4975.37 6230.71,4975.37 6363.43,5108.09 6363.43,5288.8 U3.7@6476.38,5401.75
TIM3CH3: U1.65 U3.11 | length 1485.8
  Top Layer w10: U1.65@5739.07,5103.43 5811.02,5103.43 v1@5821.06,5093.39
  Bottom Layer w10: v1@5828.02,5094.72 5854.85,5121.54 5854.85,5137.07 6036.81,5319.03 6036.81,5651.51 6052.09,5666.79 6070.44,5666.79 6073.51,5669.86 6073.51,5703.75 6219.63,5849.87 6328.56,5849.87 6358.05,5820.37 6358.05,5658.6 6367.22,5649.44 6447.62,5649.44 6450.13,5646.92 6456.62,5646.92 6471.04,5632.5 U3.11@6471.04,5597.2
  other v1: 5820.99,5093.84
TIM3CH4: U1.66 U3.6 | length 616.7
  Top Layer w10: U1.66@5742.98,5122.11 5822.9,5122.11 6045.44,5344.65 6258.64,5344.65 U3.6@6264.92,5338.37
U2RX: J12.4 U1.26 | length 1986.7
  Top Layer w10: J12.4@3889.35,5384.33 3893.59,5380.09 3961.36,5380.09 ; 3961.36,5378.68 3962.77,4919.84 4133.16,4749.45 4470.3,4749.45 4626.88,4592.87 5036.62,4592.87 U1.26@5209.71,4765.95
U2TX: J12.3 U1.25 | length 2076
  Top Layer w10: J12.3@3891.08,5482.13 3898.15,5489.2 3964.48,5489.2 3980.02,5473.66 3980.02,4939.25 4138.76,4780.51 4477.4,4780.51 4643.58,4614.33 5024.99,4614.33 5032.06,4621.4 5032.06,4708.3 U1.25@5150.02,4826.27
VDDA: C4.1 R5.2 R6.2 U1.22 | length 353.9
  Top Layer w10: R5.2@4962.74,4652.42 4966.5,4656.18 4966.5,4749.05 4997.25,4749.05 R6.2@5061.25,4813.05 ; R6.2@5063.13,4808.66 5102.06,4847.58 5102.06,4872.39 5111.72,4882.06 5136.53,4882.06 5139.06,4884.58 U1.22@5151.6,4884.58
VIN: C9.2 C10.2 J8.1 MOS1.2 R9.2 R10.1 U4.2 U4.3 | length 3615.4
  Top Layer w10: MOS1.2@4208.79,3598.88 4400.79,3790.88 U4.2@4400.79,3854.88 ; MOS1.2@4210.04,3598.88 4297.26,3511.66 R9.2@4432.8,3511.66 ; v1(4328.45,4297.43) 4328.45,4272.06 C10.2@4357.05,4243.46 ; U4.2@4400,3868.24 4400,3918.16 v1@4404.18,3922.34 ; U4.2@4402.54,3853.81 U4.3@4424.48,3853.81 ; R9.2@4434.68,3511.03 4530.05,3511.03 R10.1@4531.31,3512.28
  Top Layer w40: C10.2@4361.52,4243.07 4362.08,4243.06 4362.08,4273.11 4484.08,4395.1 C9.2@4502.22,4395.1 ; C9.2@4511.93,4402.57 4523.58,4414.22 4603.59,4414.22 v1@4638.71,4379.1 ; v1(5950.18,4734.35) 5958.65,4734.35 5968.59,4724.41 6293.53,4724.41 6316.4,4701.54 6316.4,4688.8 6353.62,4651.58 6453.67,4651.58 J8.1@6460.26,4644.99
  VCC w40: v1(4328.45,4297.43) 4328.45,3995.04 v1@4401.6,3921.89 ; v1@4642.16,4385.61 5367.67,4385.61 5454.09,4472.03 5687.86,4472.03 v1(5950.18,4734.35)
  other v1: 4404.18,3921.22 4639.96,4376.59
VREF+: R6.1 U1.21 | length 102.1
  Top Layer w10: R6.1@5054.89,4885.7 5090.59,4885.7 5110.11,4905.23 U1.21@5148.87,4905.23
pads on no net: IC1.1 IC1.6 IC1.7 IC1.9 IC1.10 IC1.12 J4.3 J7.1 J7.2 J7.3 SW1.3 U1.5 U1.6 U1.7 U1.8 U1.9 U1.15 U1.16 U1.17 U1.18 U1.23 U1.24 U1.29 U1.30 U1.34 U1.38 U1.39 U1.44 U1.45 U1.46 U1.47 U1.48 U1.49 U1.52 U1.53 U1.55 U1.56 U1.63 U1.64 U1.67 U1.70 U1.71 U1.73 U1.78 U1.79 U1.80 U1.95 U1.96 U1.101 U2.4 U4.6 U5.3 U6.4

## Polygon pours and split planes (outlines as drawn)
GND on Top Layer (solid, remove dead copper, pour order 0): 6235.63,4925.03 6791.2,4925.03 6791.2,3468.8 6235.63,3468.8
GND on Bottom Layer (solid, remove dead copper, pour order 4): 3478.2,7531.38 7831.95,7531.38 7831.95,3098.64 3478.2,3098.64
GND on GND (solid, remove dead copper): 3774.53,7274.78 7466.83,7274.78 7466.83,3000 3774.53,3000
GND on VCC (solid, remove dead copper): 3000,8111.34 7511.71,8111.34 7511.71,3056.64 3000,3056.64
GND on Top Layer (solid, remove dead copper, pour order 2): 3425.99,7518.86 7570,7518.86 7570,3288.05 3425.99,3288.05

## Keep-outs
Board Outline Layer:
  lines w10: 3802.55,3457.06 6802.55,3457.06 6802.84,4915.29 7173.66,4911.77 7171.81,5802.02 6806.8,5797.07 6802.55,7257.06 3802.55,7257.06 3802.55,3457.06

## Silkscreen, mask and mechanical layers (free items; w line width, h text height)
Mechanical Layer:
  lines w10: 6802.58,4914.78 7170.61,4913.74 ; 6807.5,5797.91 7170.61,5798.97 7170.61,5791.48 ; 7169.78,5799.39 7169.59,4925.32 7170.21,4913.02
